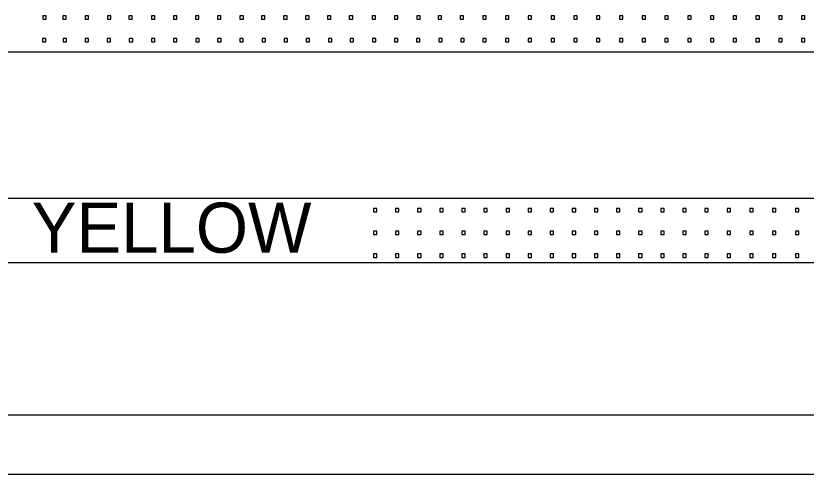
# Model space of a CAD drawing. Extents: x 10000 to 10825, y 10000 to 10530.
# Drawn here: x 10554.1 to 10609.2, y 10121.1 to 10153.1 of the extents above; entities that cross this region are included whole.
import ezdxf

# ---------------------------------------------------------------- set-up
doc = ezdxf.new("R2010")
doc.units = 0
doc.layers.add('Default', color=7, linetype='Continuous')
doc.layers.add('TextStructures', color=7, linetype='Continuous')

msp = doc.modelspace()

# ---------------------------------------------------------------- linework, layer by layer
at = {"layer": 'Default'}
for p, q in [((10490.187, 10150.62), (10784.11, 10150.62)), ((10490.187, 10140.399), (10784.11, 10140.399)), ((10490.187, 10135.911), (10784.11, 10135.911)), ((10490.187, 10125.289), (10784.11, 10125.289)), ((10490.187, 10121.141), (10784.11, 10121.141))]:
    msp.add_line(p, q, dxfattribs=at)
for points in [[(10556.218, 10152.887), (10556.218, 10153.127), (10555.982, 10153.124), (10555.982, 10152.887), (10556.218, 10152.887)], [(10557.624, 10152.887), (10557.624, 10153.127), (10557.387, 10153.124), (10557.387, 10152.887), (10557.624, 10152.887)], [(10559.178, 10152.887), (10559.178, 10153.127), (10558.942, 10153.124), (10558.942, 10152.887), (10559.178, 10152.887)], [(10560.733, 10152.887), (10560.733, 10153.127), (10560.496, 10153.124), (10560.496, 10152.887), (10560.733, 10152.887)], [(10562.224, 10152.887), (10562.224, 10153.127), (10561.987, 10153.124), (10561.987, 10152.887), (10562.224, 10152.887)], [(10563.8, 10152.887), (10563.8, 10153.127), (10563.563, 10153.124), (10563.563, 10152.887), (10563.8, 10152.887)], [(10565.333, 10152.887), (10565.333, 10153.127), (10565.096, 10153.124), (10565.096, 10152.887), (10565.333, 10152.887)], [(10566.866, 10152.887), (10566.866, 10153.127), (10566.63, 10153.124), (10566.63, 10152.887), (10566.866, 10152.887)], [(10568.399, 10152.887), (10568.399, 10153.127), (10568.163, 10153.124), (10568.163, 10152.887), (10568.399, 10152.887)], [(10569.975, 10152.887), (10569.975, 10153.127), (10569.739, 10153.124), (10569.739, 10152.887), (10569.975, 10152.887)], [(10571.466, 10152.887), (10571.466, 10153.127), (10571.229, 10153.124), (10571.229, 10152.887), (10571.466, 10152.887)], [(10573.021, 10152.887), (10573.021, 10153.127), (10572.784, 10153.124), (10572.784, 10152.887), (10573.021, 10152.887)], [(10574.554, 10152.887), (10574.554, 10153.127), (10574.317, 10153.124), (10574.317, 10152.887), (10574.554, 10152.887)], [(10576.087, 10152.887), (10576.087, 10153.127), (10575.851, 10153.124), (10575.851, 10152.887), (10576.087, 10152.887)], [(10577.599, 10152.887), (10577.599, 10153.127), (10577.363, 10153.124), (10577.363, 10152.887), (10577.599, 10152.887)], [(10579.197, 10152.887), (10579.197, 10153.127), (10578.96, 10153.124), (10578.96, 10152.887), (10579.197, 10152.887)], [(10580.751, 10152.887), (10580.751, 10153.127), (10580.514, 10153.124), (10580.514, 10152.887), (10580.751, 10152.887)], [(10582.306, 10152.887), (10582.306, 10153.127), (10582.069, 10153.124), (10582.069, 10152.887), (10582.306, 10152.887)], [(10583.796, 10152.887), (10583.796, 10153.127), (10583.56, 10153.124), (10583.56, 10152.887), (10583.796, 10152.887)], [(10585.33, 10152.887), (10585.33, 10153.127), (10585.093, 10153.124), (10585.093, 10152.887), (10585.33, 10152.887)], [(10586.908, 10152.887), (10586.908, 10153.127), (10586.671, 10153.124), (10586.671, 10152.887), (10586.908, 10152.887)], [(10586.908, 10152.887), (10586.908, 10153.127), (10586.671, 10153.124), (10586.671, 10152.887), (10586.908, 10152.887)], [(10588.497, 10152.887), (10588.497, 10153.127), (10588.261, 10153.124), (10588.261, 10152.887), (10588.497, 10152.887)], [(10588.497, 10152.887), (10588.497, 10153.127), (10588.261, 10153.124), (10588.261, 10152.887), (10588.497, 10152.887)], [(10590.084, 10152.887), (10590.084, 10153.127), (10589.847, 10153.124), (10589.847, 10152.887), (10590.084, 10152.887)], [(10590.084, 10152.887), (10590.084, 10153.127), (10589.847, 10153.124), (10589.847, 10152.887), (10590.084, 10152.887)], [(10591.674, 10152.887), (10591.674, 10153.127), (10591.437, 10153.124), (10591.437, 10152.887), (10591.674, 10152.887)], [(10591.674, 10152.887), (10591.674, 10153.127), (10591.437, 10153.124), (10591.437, 10152.887), (10591.674, 10152.887)], [(10593.26, 10152.887), (10593.26, 10153.127), (10593.023, 10153.124), (10593.023, 10152.887), (10593.26, 10152.887)], [(10593.26, 10152.887), (10593.26, 10153.127), (10593.023, 10153.124), (10593.023, 10152.887), (10593.26, 10152.887)], [(10594.85, 10152.887), (10594.85, 10153.127), (10594.613, 10153.124), (10594.613, 10152.887), (10594.85, 10152.887)], [(10594.85, 10152.887), (10594.85, 10153.127), (10594.613, 10153.124), (10594.613, 10152.887), (10594.85, 10152.887)], [(10596.436, 10152.887), (10596.436, 10153.127), (10596.2, 10153.124), (10596.2, 10152.887), (10596.436, 10152.887)], [(10596.436, 10152.887), (10596.436, 10153.127), (10596.2, 10153.124), (10596.2, 10152.887), (10596.436, 10152.887)], [(10598.026, 10152.887), (10598.026, 10153.127), (10597.789, 10153.124), (10597.789, 10152.887), (10598.026, 10152.887)], [(10598.026, 10152.887), (10598.026, 10153.127), (10597.789, 10153.124), (10597.789, 10152.887), (10598.026, 10152.887)], [(10599.612, 10152.887), (10599.612, 10153.127), (10599.376, 10153.124), (10599.376, 10152.887), (10599.612, 10152.887)], [(10599.612, 10152.887), (10599.612, 10153.127), (10599.376, 10153.124), (10599.376, 10152.887), (10599.612, 10152.887)], [(10601.202, 10152.887), (10601.202, 10153.127), (10600.965, 10153.124), (10600.965, 10152.887), (10601.202, 10152.887)], [(10601.202, 10152.887), (10601.202, 10153.127), (10600.965, 10153.124), (10600.965, 10152.887), (10601.202, 10152.887)], [(10602.788, 10152.887), (10602.788, 10153.127), (10602.552, 10153.124), (10602.552, 10152.887), (10602.788, 10152.887)], [(10602.788, 10152.887), (10602.788, 10153.127), (10602.552, 10153.124), (10602.552, 10152.887), (10602.788, 10152.887)], [(10604.378, 10152.887), (10604.378, 10153.127), (10604.142, 10153.124), (10604.142, 10152.887), (10604.378, 10152.887)], [(10604.378, 10152.887), (10604.378, 10153.127), (10604.142, 10153.124), (10604.142, 10152.887), (10604.378, 10152.887)], [(10605.965, 10152.887), (10605.965, 10153.127), (10605.728, 10153.124), (10605.728, 10152.887), (10605.965, 10152.887)], [(10605.965, 10152.887), (10605.965, 10153.127), (10605.728, 10153.124), (10605.728, 10152.887), (10605.965, 10152.887)], [(10607.554, 10152.887), (10607.554, 10153.127), (10607.318, 10153.124), (10607.318, 10152.887), (10607.554, 10152.887)], [(10607.554, 10152.887), (10607.554, 10153.127), (10607.318, 10153.124), (10607.318, 10152.887), (10607.554, 10152.887)], [(10609.141, 10152.887), (10609.141, 10153.127), (10608.904, 10153.124), (10608.904, 10152.887), (10609.141, 10152.887)], [(10609.141, 10152.887), (10609.141, 10153.127), (10608.904, 10153.124), (10608.904, 10152.887), (10609.141, 10152.887)], [(10556.203, 10151.299), (10556.203, 10151.538), (10555.966, 10151.537), (10555.966, 10151.299), (10556.203, 10151.299)], [(10557.633, 10151.299), (10557.633, 10151.538), (10557.397, 10151.537), (10557.397, 10151.299), (10557.633, 10151.299)], [(10559.183, 10151.299), (10559.183, 10151.538), (10558.946, 10151.537), (10558.946, 10151.299), (10559.183, 10151.299)], [(10560.706, 10151.299), (10560.706, 10151.538), (10560.47, 10151.537), (10560.47, 10151.299), (10560.706, 10151.299)], [(10562.256, 10151.299), (10562.256, 10151.538), (10562.02, 10151.537), (10562.02, 10151.299), (10562.256, 10151.299)], [(10563.806, 10151.299), (10563.806, 10151.538), (10563.569, 10151.537), (10563.569, 10151.299), (10563.806, 10151.299)], [(10565.343, 10151.299), (10565.343, 10151.538), (10565.106, 10151.537), (10565.106, 10151.299), (10565.343, 10151.299)], [(10566.892, 10151.299), (10566.892, 10151.538), (10566.656, 10151.537), (10566.656, 10151.299), (10566.892, 10151.299)], [(10568.416, 10151.299), (10568.416, 10151.538), (10568.179, 10151.537), (10568.179, 10151.299), (10568.416, 10151.299)], [(10569.966, 10151.299), (10569.966, 10151.538), (10569.729, 10151.537), (10569.729, 10151.299), (10569.966, 10151.299)], [(10571.515, 10151.299), (10571.515, 10151.538), (10571.279, 10151.537), (10571.279, 10151.299), (10571.515, 10151.299)], [(10573.052, 10151.299), (10573.052, 10151.538), (10572.815, 10151.537), (10572.815, 10151.299), (10573.052, 10151.299)], [(10574.589, 10151.299), (10574.589, 10151.538), (10574.352, 10151.537), (10574.352, 10151.299), (10574.589, 10151.299)], [(10576.138, 10151.299), (10576.138, 10151.538), (10575.902, 10151.537), (10575.902, 10151.299), (10576.138, 10151.299)], [(10577.662, 10151.299), (10577.662, 10151.538), (10577.425, 10151.537), (10577.425, 10151.299), (10577.662, 10151.299)], [(10579.212, 10151.299), (10579.212, 10151.538), (10578.975, 10151.537), (10578.975, 10151.299), (10579.212, 10151.299)], [(10580.748, 10151.299), (10580.748, 10151.538), (10580.511, 10151.537), (10580.511, 10151.299), (10580.748, 10151.299)], [(10582.285, 10151.299), (10582.285, 10151.538), (10582.048, 10151.537), (10582.048, 10151.299), (10582.285, 10151.299)], [(10583.848, 10151.299), (10583.848, 10151.538), (10583.611, 10151.537), (10583.611, 10151.299), (10583.848, 10151.299)], [(10585.371, 10151.299), (10585.371, 10151.538), (10585.134, 10151.537), (10585.134, 10151.299), (10585.371, 10151.299)], [(10586.908, 10151.299), (10586.908, 10151.538), (10586.671, 10151.537), (10586.671, 10151.299), (10586.908, 10151.299)], [(10586.908, 10151.299), (10586.908, 10151.538), (10586.671, 10151.537), (10586.671, 10151.299), (10586.908, 10151.299)], [(10588.497, 10151.299), (10588.497, 10151.538), (10588.261, 10151.537), (10588.261, 10151.299), (10588.497, 10151.299)], [(10588.497, 10151.299), (10588.497, 10151.538), (10588.261, 10151.537), (10588.261, 10151.299), (10588.497, 10151.299)], [(10590.084, 10151.299), (10590.084, 10151.538), (10589.847, 10151.537), (10589.847, 10151.299), (10590.084, 10151.299)], [(10590.084, 10151.299), (10590.084, 10151.538), (10589.847, 10151.537), (10589.847, 10151.299), (10590.084, 10151.299)], [(10591.674, 10151.299), (10591.674, 10151.538), (10591.437, 10151.537), (10591.437, 10151.299), (10591.674, 10151.299)], [(10591.674, 10151.299), (10591.674, 10151.538), (10591.437, 10151.537), (10591.437, 10151.299), (10591.674, 10151.299)], [(10593.26, 10151.299), (10593.26, 10151.538), (10593.023, 10151.537), (10593.023, 10151.299), (10593.26, 10151.299)], [(10593.26, 10151.299), (10593.26, 10151.538), (10593.023, 10151.537), (10593.023, 10151.299), (10593.26, 10151.299)], [(10594.85, 10151.299), (10594.85, 10151.538), (10594.613, 10151.537), (10594.613, 10151.299), (10594.85, 10151.299)], [(10594.85, 10151.299), (10594.85, 10151.538), (10594.613, 10151.537), (10594.613, 10151.299), (10594.85, 10151.299)], [(10596.436, 10151.299), (10596.436, 10151.538), (10596.2, 10151.537), (10596.2, 10151.299), (10596.436, 10151.299)], [(10596.436, 10151.299), (10596.436, 10151.538), (10596.2, 10151.537), (10596.2, 10151.299), (10596.436, 10151.299)], [(10598.026, 10151.299), (10598.026, 10151.538), (10597.789, 10151.537), (10597.789, 10151.299), (10598.026, 10151.299)], [(10598.026, 10151.299), (10598.026, 10151.538), (10597.789, 10151.537), (10597.789, 10151.299), (10598.026, 10151.299)], [(10599.612, 10151.299), (10599.612, 10151.538), (10599.376, 10151.537), (10599.376, 10151.299), (10599.612, 10151.299)], [(10599.612, 10151.299), (10599.612, 10151.538), (10599.376, 10151.537), (10599.376, 10151.299), (10599.612, 10151.299)], [(10601.202, 10151.299), (10601.202, 10151.538), (10600.965, 10151.537), (10600.965, 10151.299), (10601.202, 10151.299)], [(10601.202, 10151.299), (10601.202, 10151.538), (10600.965, 10151.537), (10600.965, 10151.299), (10601.202, 10151.299)], [(10602.788, 10151.299), (10602.788, 10151.538), (10602.552, 10151.537), (10602.552, 10151.299), (10602.788, 10151.299)], [(10602.788, 10151.299), (10602.788, 10151.538), (10602.552, 10151.537), (10602.552, 10151.299), (10602.788, 10151.299)], [(10604.378, 10151.299), (10604.378, 10151.538), (10604.142, 10151.537), (10604.142, 10151.299), (10604.378, 10151.299)], [(10604.378, 10151.299), (10604.378, 10151.538), (10604.142, 10151.537), (10604.142, 10151.299), (10604.378, 10151.299)], [(10605.965, 10151.299), (10605.965, 10151.538), (10605.728, 10151.537), (10605.728, 10151.299), (10605.965, 10151.299)], [(10605.965, 10151.299), (10605.965, 10151.538), (10605.728, 10151.537), (10605.728, 10151.299), (10605.965, 10151.299)], [(10607.554, 10151.299), (10607.554, 10151.538), (10607.318, 10151.537), (10607.318, 10151.299), (10607.554, 10151.299)], [(10607.554, 10151.299), (10607.554, 10151.538), (10607.318, 10151.537), (10607.318, 10151.299), (10607.554, 10151.299)], [(10609.141, 10151.299), (10609.141, 10151.538), (10608.904, 10151.537), (10608.904, 10151.299), (10609.141, 10151.299)], [(10609.141, 10151.299), (10609.141, 10151.538), (10608.904, 10151.537), (10608.904, 10151.299), (10609.141, 10151.299)], [(10579.284, 10139.448), (10579.284, 10139.688), (10579.048, 10139.687), (10579.048, 10139.448), (10579.284, 10139.448)], [(10580.826, 10139.448), (10580.826, 10139.688), (10580.589, 10139.687), (10580.589, 10139.448), (10580.826, 10139.448)], [(10582.367, 10139.448), (10582.367, 10139.688), (10582.131, 10139.687), (10582.131, 10139.448), (10582.367, 10139.448)], [(10583.909, 10139.448), (10583.909, 10139.688), (10583.672, 10139.687), (10583.672, 10139.448), (10583.909, 10139.448)], [(10585.45, 10139.448), (10585.45, 10139.688), (10585.213, 10139.687), (10585.213, 10139.448), (10585.45, 10139.448)], [(10586.991, 10139.448), (10586.991, 10139.688), (10586.755, 10139.687), (10586.755, 10139.448), (10586.991, 10139.448)], [(10588.533, 10139.448), (10588.533, 10139.688), (10588.296, 10139.687), (10588.296, 10139.448), (10588.533, 10139.448)], [(10590.074, 10139.448), (10590.074, 10139.688), (10589.838, 10139.687), (10589.838, 10139.448), (10590.074, 10139.448)], [(10591.616, 10139.448), (10591.616, 10139.688), (10591.379, 10139.687), (10591.379, 10139.448), (10591.616, 10139.448)], [(10593.157, 10139.448), (10593.157, 10139.688), (10592.92, 10139.687), (10592.92, 10139.448), (10593.157, 10139.448)], [(10594.698, 10139.448), (10594.698, 10139.688), (10594.462, 10139.687), (10594.462, 10139.448), (10594.698, 10139.448)], [(10596.24, 10139.448), (10596.24, 10139.688), (10596.003, 10139.687), (10596.003, 10139.448), (10596.24, 10139.448)], [(10597.781, 10139.448), (10597.781, 10139.688), (10597.545, 10139.687), (10597.545, 10139.448), (10597.781, 10139.448)], [(10599.323, 10139.448), (10599.323, 10139.688), (10599.086, 10139.687), (10599.086, 10139.448), (10599.323, 10139.448)], [(10600.864, 10139.448), (10600.864, 10139.688), (10600.627, 10139.687), (10600.627, 10139.448), (10600.864, 10139.448)], [(10602.405, 10139.448), (10602.405, 10139.688), (10602.169, 10139.687), (10602.169, 10139.448), (10602.405, 10139.448)], [(10603.947, 10139.448), (10603.947, 10139.688), (10603.71, 10139.687), (10603.71, 10139.448), (10603.947, 10139.448)], [(10603.947, 10139.448), (10603.947, 10139.688), (10603.71, 10139.687), (10603.71, 10139.448), (10603.947, 10139.448)], [(10605.537, 10139.448), (10605.537, 10139.688), (10605.3, 10139.687), (10605.3, 10139.448), (10605.537, 10139.448)], [(10605.537, 10139.448), (10605.537, 10139.688), (10605.3, 10139.687), (10605.3, 10139.448), (10605.537, 10139.448)], [(10607.123, 10139.448), (10607.123, 10139.688), (10606.886, 10139.687), (10606.886, 10139.448), (10607.123, 10139.448)], [(10607.123, 10139.448), (10607.123, 10139.688), (10606.886, 10139.687), (10606.886, 10139.448), (10607.123, 10139.448)], [(10608.713, 10139.448), (10608.713, 10139.688), (10608.476, 10139.687), (10608.476, 10139.448), (10608.713, 10139.448)], [(10608.713, 10139.448), (10608.713, 10139.688), (10608.476, 10139.687), (10608.476, 10139.448), (10608.713, 10139.448)], [(10579.284, 10137.861), (10579.284, 10138.1), (10579.048, 10138.099), (10579.048, 10137.861), (10579.284, 10137.861)], [(10580.826, 10137.861), (10580.826, 10138.1), (10580.589, 10138.099), (10580.589, 10137.861), (10580.826, 10137.861)], [(10582.367, 10137.861), (10582.367, 10138.1), (10582.131, 10138.099), (10582.131, 10137.861), (10582.367, 10137.861)], [(10583.909, 10137.861), (10583.909, 10138.1), (10583.672, 10138.099), (10583.672, 10137.861), (10583.909, 10137.861)], [(10585.45, 10137.861), (10585.45, 10138.1), (10585.213, 10138.099), (10585.213, 10137.861), (10585.45, 10137.861)], [(10586.991, 10137.861), (10586.991, 10138.1), (10586.755, 10138.099), (10586.755, 10137.861), (10586.991, 10137.861)], [(10588.533, 10137.861), (10588.533, 10138.1), (10588.296, 10138.099), (10588.296, 10137.861), (10588.533, 10137.861)], [(10590.074, 10137.861), (10590.074, 10138.1), (10589.838, 10138.099), (10589.838, 10137.861), (10590.074, 10137.861)], [(10591.616, 10137.861), (10591.616, 10138.1), (10591.379, 10138.099), (10591.379, 10137.861), (10591.616, 10137.861)], [(10593.157, 10137.861), (10593.157, 10138.1), (10592.92, 10138.099), (10592.92, 10137.861), (10593.157, 10137.861)], [(10594.698, 10137.861), (10594.698, 10138.1), (10594.462, 10138.099), (10594.462, 10137.861), (10594.698, 10137.861)], [(10596.24, 10137.861), (10596.24, 10138.1), (10596.003, 10138.099), (10596.003, 10137.861), (10596.24, 10137.861)], [(10597.781, 10137.861), (10597.781, 10138.1), (10597.545, 10138.099), (10597.545, 10137.861), (10597.781, 10137.861)], [(10599.323, 10137.861), (10599.323, 10138.1), (10599.086, 10138.099), (10599.086, 10137.861), (10599.323, 10137.861)], [(10600.864, 10137.861), (10600.864, 10138.1), (10600.627, 10138.099), (10600.627, 10137.861), (10600.864, 10137.861)], [(10602.405, 10137.861), (10602.405, 10138.1), (10602.169, 10138.099), (10602.169, 10137.861), (10602.405, 10137.861)], [(10603.947, 10137.861), (10603.947, 10138.1), (10603.71, 10138.099), (10603.71, 10137.861), (10603.947, 10137.861)], [(10603.947, 10137.861), (10603.947, 10138.1), (10603.71, 10138.099), (10603.71, 10137.861), (10603.947, 10137.861)], [(10605.537, 10137.861), (10605.537, 10138.1), (10605.3, 10138.099), (10605.3, 10137.861), (10605.537, 10137.861)], [(10605.537, 10137.861), (10605.537, 10138.1), (10605.3, 10138.099), (10605.3, 10137.861), (10605.537, 10137.861)], [(10607.123, 10137.861), (10607.123, 10138.1), (10606.886, 10138.099), (10606.886, 10137.861), (10607.123, 10137.861)], [(10607.123, 10137.861), (10607.123, 10138.1), (10606.886, 10138.099), (10606.886, 10137.861), (10607.123, 10137.861)], [(10608.713, 10137.861), (10608.713, 10138.1), (10608.476, 10138.099), (10608.476, 10137.861), (10608.713, 10137.861)], [(10608.713, 10137.861), (10608.713, 10138.1), (10608.476, 10138.099), (10608.476, 10137.861), (10608.713, 10137.861)], [(10579.284, 10136.272), (10579.284, 10136.512), (10579.048, 10136.511), (10579.048, 10136.272), (10579.284, 10136.272)], [(10580.826, 10136.272), (10580.826, 10136.512), (10580.589, 10136.511), (10580.589, 10136.272), (10580.826, 10136.272)], [(10582.367, 10136.272), (10582.367, 10136.512), (10582.131, 10136.511), (10582.131, 10136.272), (10582.367, 10136.272)], [(10583.909, 10136.272), (10583.909, 10136.512), (10583.672, 10136.511), (10583.672, 10136.272), (10583.909, 10136.272)], [(10585.45, 10136.272), (10585.45, 10136.512), (10585.213, 10136.511), (10585.213, 10136.272), (10585.45, 10136.272)], [(10586.991, 10136.272), (10586.991, 10136.512), (10586.755, 10136.511), (10586.755, 10136.272), (10586.991, 10136.272)], [(10588.533, 10136.272), (10588.533, 10136.512), (10588.296, 10136.511), (10588.296, 10136.272), (10588.533, 10136.272)], [(10590.074, 10136.272), (10590.074, 10136.512), (10589.838, 10136.511), (10589.838, 10136.272), (10590.074, 10136.272)], [(10591.616, 10136.272), (10591.616, 10136.512), (10591.379, 10136.511), (10591.379, 10136.272), (10591.616, 10136.272)], [(10593.157, 10136.272), (10593.157, 10136.512), (10592.92, 10136.511), (10592.92, 10136.272), (10593.157, 10136.272)], [(10594.698, 10136.272), (10594.698, 10136.512), (10594.462, 10136.511), (10594.462, 10136.272), (10594.698, 10136.272)], [(10596.24, 10136.272), (10596.24, 10136.512), (10596.003, 10136.511), (10596.003, 10136.272), (10596.24, 10136.272)], [(10597.781, 10136.272), (10597.781, 10136.512), (10597.545, 10136.511), (10597.545, 10136.272), (10597.781, 10136.272)], [(10599.323, 10136.272), (10599.323, 10136.512), (10599.086, 10136.511), (10599.086, 10136.272), (10599.323, 10136.272)], [(10600.864, 10136.272), (10600.864, 10136.512), (10600.627, 10136.511), (10600.627, 10136.272), (10600.864, 10136.272)], [(10602.405, 10136.272), (10602.405, 10136.512), (10602.169, 10136.511), (10602.169, 10136.272), (10602.405, 10136.272)], [(10603.947, 10136.272), (10603.947, 10136.512), (10603.71, 10136.511), (10603.71, 10136.272), (10603.947, 10136.272)], [(10603.947, 10136.272), (10603.947, 10136.512), (10603.71, 10136.511), (10603.71, 10136.272), (10603.947, 10136.272)], [(10605.537, 10136.272), (10605.537, 10136.512), (10605.3, 10136.511), (10605.3, 10136.272), (10605.537, 10136.272)], [(10605.537, 10136.272), (10605.537, 10136.512), (10605.3, 10136.511), (10605.3, 10136.272), (10605.537, 10136.272)], [(10607.123, 10136.272), (10607.123, 10136.512), (10606.886, 10136.511), (10606.886, 10136.272), (10607.123, 10136.272)], [(10607.123, 10136.272), (10607.123, 10136.512), (10606.886, 10136.511), (10606.886, 10136.272), (10607.123, 10136.272)], [(10608.713, 10136.272), (10608.713, 10136.512), (10608.476, 10136.511), (10608.476, 10136.272), (10608.713, 10136.272)], [(10608.713, 10136.272), (10608.713, 10136.512), (10608.476, 10136.511), (10608.476, 10136.272), (10608.713, 10136.272)]]:
    msp.add_lwpolyline(points, dxfattribs=at)

# ---------------------------------------------------------------- texts
at = {"layer": 'TextStructures'}
msp.add_text('YELLOW', height=3.5, rotation=0.0007, dxfattribs=at).set_placement((10555.213, 10136.592))

doc.saveas('drawing.dxf')
